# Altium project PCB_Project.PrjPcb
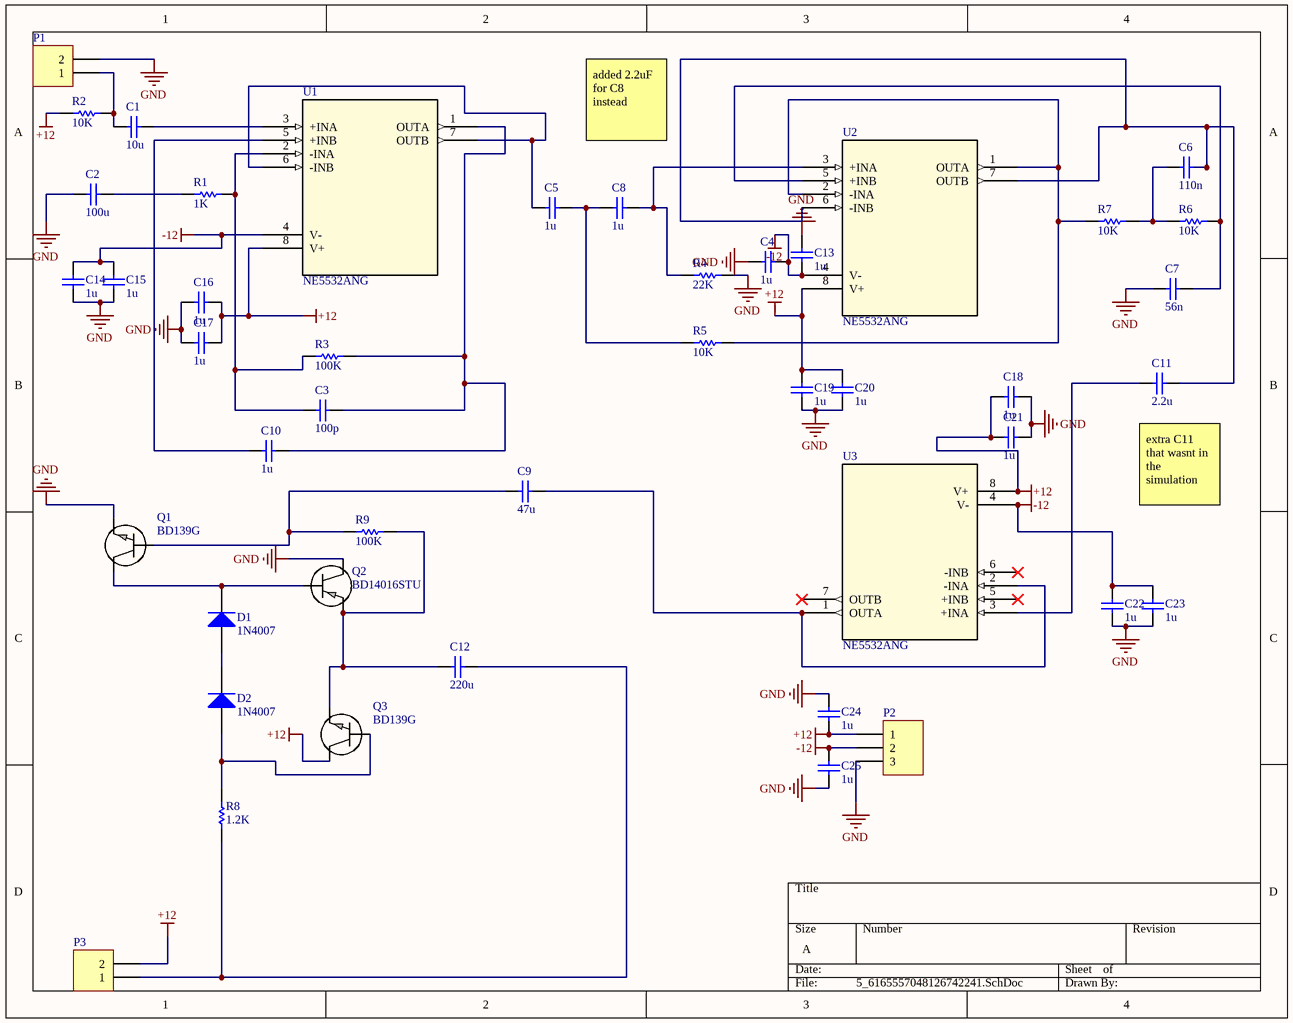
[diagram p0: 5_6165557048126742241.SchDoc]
1 sheet, 45 parts. Net scope: global (net labels, ports and power ports of the same name join across sheets).
Board file: PCB1.PcbDoc

## Sheet 5_6165557048126742241.SchDoc
size A; SheetNumber: 1; SheetTotal: 1

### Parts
C1  value 10u  [CAP_RDE5C1H104J2K1H03B]  (hidden comment: Capacitor)
C2  value 100u  [CAP_RDE5C1H104J2K1H03B]  (hidden comment: Capacitor)
C3  value 100p  [CAP_RDE5C1H104J2K1H03B]  (hidden comment: Capacitor)
C4  value 1u  [CAP_RDE5C1H104J2K1H03B]  (hidden comment: Capacitor)
C5  value 1u  [CAP_RDE5C1H104J2K1H03B]  (hidden comment: Capacitor)
C6  value 110n  [CAP_RDE5C1H104J2K1H03B]  (hidden comment: Capacitor)
C7  value 56n  [CAP_RDE5C1H104J2K1H03B]  (hidden comment: Capacitor)
C8  value 1u  [CAP_RDE5C1H104J2K1H03B]  (hidden comment: Capacitor)
C9  value 47u  [CAP_RDE5C1H104J2K1H03B]  (hidden comment: Capacitor)
C10  value 1u  [CAP_RDE5C1H104J2K1H03B]  (hidden comment: Capacitor)
C11  value 2.2u  [CAP_RDE5C1H104J2K1H03B]  (hidden comment: Capacitor)
C12  value 220u  [CAP_RDE5C1H104J2K1H03B]  (hidden comment: Capacitor)
C13  value 1u  [CAP_RDE5C1H104J2K1H03B]  (hidden comment: Capacitor)
C14  value 1u  [CAP_RDE5C1H104J2K1H03B]  (hidden comment: Capacitor)
C15  value 1u  [CAP_RDE5C1H104J2K1H03B]  (hidden comment: Capacitor)
C16  value 1u  [CAP_RDE5C1H104J2K1H03B]  (hidden comment: Capacitor)
C17  value 1u  [CAP_RDE5C1H104J2K1H03B]  (hidden comment: Capacitor)
C18  value 1u  [CAP_RDE5C1H104J2K1H03B]  (hidden comment: Capacitor)
C19  value 1u  [CAP_RDE5C1H104J2K1H03B]  (hidden comment: Capacitor)
C20  value 1u  [CAP_RDE5C1H104J2K1H03B]  (hidden comment: Capacitor)
C21  value 1u  [CAP_RDE5C1H104J2K1H03B]  (hidden comment: Capacitor)
C22  value 1u  [CAP_RDE5C1H104J2K1H03B]  (hidden comment: Capacitor)
C23  value 1u  [CAP_RDE5C1H104J2K1H03B]  (hidden comment: Capacitor)
C24  value 1u  [CAP_RDE5C1H104J2K1H03B]  (hidden comment: Capacitor)
C25  value 1u  [CAP_RDE5C1H104J2K1H03B]  (hidden comment: Capacitor)
D1  1N4007  [My_DO41]
D2  1N4007  [My_DO41]
P1  Header 2  [My_1X02]  (value not drawn)
P2  Header 3  [My_CN3]  (value not drawn)
P3  Header 2  [My_1X02]  (value not drawn)
Q1  BD139G  [SOT-32_STM]
Q2  BD14016STU  [SOT-32_STM]
Q3  BD139G  [SOT-32_STM]
R1  value 1K  [RESAD700W45L350D185]  (hidden comment: Resistor)
R2  value 10K  [RESAD700W45L350D185]  (hidden comment: Resistor)
R3  value 100K  [RESAD700W45L350D185]  (hidden comment: Resistor)
R4  value 22K  [RESAD700W45L350D185]  (hidden comment: Resistor)
R5  value 10K  [RESAD700W45L350D185]  (hidden comment: Resistor)
R6  value 10K  [RESAD700W45L350D185]  (hidden comment: Resistor)
R7  value 10K  [RESAD700W45L350D185]  (hidden comment: Resistor)
R8  value 1.2K  [RESAD700W45L350D185]  (hidden comment: Resistor)
R9  value 100K  [RESAD700W45L350D185]  (hidden comment: Resistor)
U1  NE5532ANG  [P8]
U2  NE5532ANG  [P8]
U3  NE5532ANG  [P8]

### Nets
+12: C16.2 C17.2 C18.2 C19.2 C20.2 C21.2 C24.1 P2.1 P3.2 Q3.2(C) R2.1 U1.8(V+) U2.8(V+) U3.8(V+)
-12: C4.1 C13.1 C14.2 C15.2 C22.2 C23.2 C25.2 P2.2 U1.4(V-) U2.4(V-) U3.4(V-)
GND: C2.1 C4.2 C7.1 C13.2 C14.1 C15.1 C16.1 C17.1 C18.1 C19.1 C20.1 C21.1 C22.1 C23.1 C24.2 C25.1 P1.2 P2.3 Q1.1(E) Q2.2(C) R4.2
NetC1_1: C1.1 P1.1 R2.2
NetC1_2: C1.2 U1.3(+INA)
NetC2_2: C2.2 R1.1
NetC3_1: C3.1 R1.2 R3.1 U1.2(-INA)
NetC3_2: C3.2 C10.2 R3.2 U1.1(OUTA)
NetC5_1: C5.1 U1.6(-INB) U1.7(OUTB)
NetC5_2: C5.2 C8.1 R5.1
NetC6_1: C6.1 R6.1 R7.2
NetC6_2: C6.2 C11.2 U2.6(-INB) U2.7(OUTB)
NetC7_2: C7.2 R6.2 U2.5(+INB)
NetC8_2: C8.2 R4.1 U2.3(+INA)
NetC9_1: C9.1 Q1.3(B) R9.1
NetC9_2: C9.2 U3.1(OUTA) U3.2(-INA)
NetC10_1: C10.1 U1.5(+INB)
NetC11_1: C11.1 U3.3(+INA)
NetC12_1: C12.1 Q2.1(E) Q3.1(E) R9.2
NetC12_2: C12.2 P3.1 R8.1
NetD1_A: D1.A D2.K
NetD1_K: D1.K Q1.2(C) Q2.3(B)
NetD2_A: D2.A Q3.3(B) R8.2
NetR5_2: R5.2 R7.1 U2.1(OUTA) U2.2(-INA)

Not connected (* = marked no-connect by the designer): U3 5(+INB)* 6(-INB)* 7(OUTB)*

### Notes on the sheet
- added 2.2uF for C8 instead
- (near C11) extra C11 that wasnt in the simulation

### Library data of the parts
C1-C25 = Capacitor: SimulationGenericComponent: True
D1 D2 = 1N4007: 1 Amp Diode; ASiD Part Number: 1n4007-AS
P1 P3 = Header 2: Header, 2-Pin; ASiD Part Number: Header 2-AS
P2 = Header 3: Header, 3-Pin; ASiD Part Number: Header 3-AS
Q1 Q3 = BD139G: No Description Available; Manufacturer_Name: onsemi
Q2 = BD14016STU: No Description Available; Manufacturer_Name: onsemi
R1-R9 = Resistor: TC1: 0; SimulationGenericComponent: True
U1-U3 = NE5532ANG: No Description Available; Manufacturer_Name: onsemi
